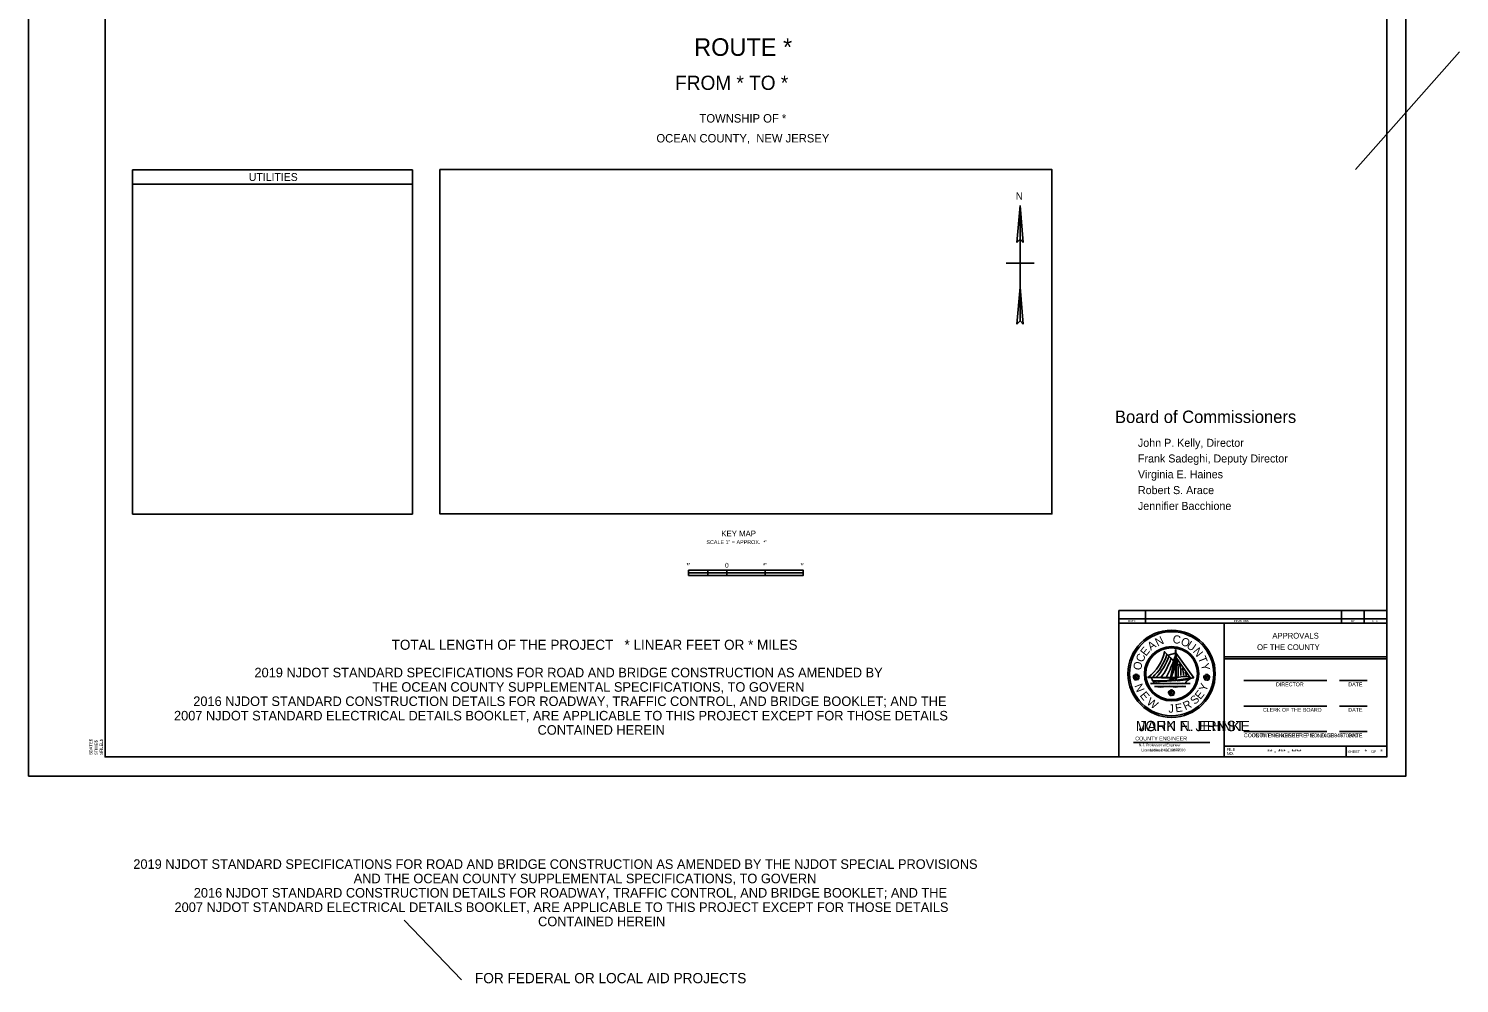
# Model space of a CAD drawing. Extents: x -51896 to -50062, y 9316 to 10514.
# Drawn here: x -51896 to -50774, y 9316 to 10064 of the extents above; entities that cross this region are included whole.
import ezdxf

# ---------------------------------------------------------------- set-up
doc = ezdxf.new("R2010")
doc.units = 0
for name, color, linetype in [('_Guidelines', 7, 'Continuous'), ('Default', 7, 'Continuous'), ('Level 1', 7, 'Continuous'), ('Level 47', 7, 'Continuous'), ('Plan - North Arrow', 7, 'Continuous'), ('TB - ON', 7, 'Continuous'), ('TB - Signed by John N Ernst', 7, 'Continuous'), ('TB - Signed by Mark F Jehnke', 7, 'Continuous')]:
    doc.layers.add(name, color=color, linetype=linetype)

msp = doc.modelspace()

# ---------------------------------------------------------------- linework, layer by layer
at = {"layer": '_Guidelines'}
for p, q in [((-50855, 9953.9), (-50773.6, 10046.3)), ((-51601.2, 9365.2), (-51556.2, 9318.4))]:
    msp.add_line(p, q, dxfattribs=at)
msp.add_lwpolyline([(-51895.6, 9478.3), (-50815.6, 9478.3), (-50815.6, 10198.3), (-51895.6, 10198.3)], close=True, dxfattribs=at)
at = {"layer": 'Default'}
msp.add_line((-51835.6, 9493.3), (-51835.6, 9503.3), dxfattribs=at)
at = {"layer": 'Level 1'}
for p, q in [((-51814.2, 9953.6), (-51594.5, 9953.6)), ((-51814.2, 9683.6), (-51814.2, 9953.6)), ((-51594.5, 9953.6), (-51594.5, 9683.6)), ((-51594.5, 9942.5), (-51814.2, 9942.5)), ((-51814.2, 9683.6), (-51594.5, 9683.6))]:
    msp.add_line(p, q, dxfattribs=at)
for points in [[(-51835.6, 10183.3), (-50830.6, 10183.3), (-50830.6, 9493.3), (-51835.6, 9493.3)], [(-51573.1, 9953.9), (-51093.1, 9953.9), (-51093.1, 9683.9), (-51573.1, 9683.9)], [(-51378.1, 9637.7), (-51363.1, 9637.7), (-51363.1, 9639.7), (-51378.1, 9639.7)], [(-51378.1, 9639.7), (-51363.1, 9639.7), (-51363.1, 9637.7), (-51378.1, 9637.7)], [(-51378.1, 9635.7), (-51363.1, 9635.7), (-51363.1, 9637.7), (-51378.1, 9637.7)], [(-51378.1, 9635.7), (-51363.1, 9635.7), (-51363.1, 9637.7), (-51378.1, 9637.7)], [(-51363.1, 9637.7), (-51348.1, 9637.7), (-51348.1, 9639.7), (-51363.1, 9639.7)], [(-51363.1, 9637.7), (-51348.1, 9637.7), (-51348.1, 9639.7), (-51363.1, 9639.7)], [(-51363.1, 9635.7), (-51348.1, 9635.7), (-51348.1, 9637.7), (-51363.1, 9637.7)], [(-51363.1, 9637.7), (-51348.1, 9637.7), (-51348.1, 9635.7), (-51363.1, 9635.7)], [(-51348.1, 9637.7), (-51318.1, 9637.7), (-51318.1, 9639.7), (-51348.1, 9639.7)], [(-51348.1, 9639.7), (-51318.1, 9639.7), (-51318.1, 9637.7), (-51348.1, 9637.7)], [(-51348.1, 9635.7), (-51318.1, 9635.7), (-51318.1, 9637.7), (-51348.1, 9637.7)], [(-51348.1, 9635.7), (-51318.1, 9635.7), (-51318.1, 9637.7), (-51348.1, 9637.7)], [(-51318.1, 9637.7), (-51288.1, 9637.7), (-51288.1, 9639.7), (-51318.1, 9639.7)], [(-51318.1, 9637.7), (-51288.1, 9637.7), (-51288.1, 9639.7), (-51318.1, 9639.7)], [(-51318.1, 9635.7), (-51288.1, 9635.7), (-51288.1, 9637.7), (-51318.1, 9637.7)], [(-51318.1, 9637.7), (-51288.1, 9637.7), (-51288.1, 9635.7), (-51318.1, 9635.7)]]:
    msp.add_lwpolyline(points, close=True, dxfattribs=at)
at = {"layer": 'Level 47'}
for p, q in [((-50831.1, 9595.4), (-50830.6, 9595.4)), ((-50830.6, 9595.4), (-50830.6, 9493.3)), ((-50830.6, 9595.4), (-50830.6, 9493.2)), ((-51005, 9575.6), (-50996.3, 9566.9)), ((-51004.8, 9575.8), (-50996.3, 9567.4)), ((-50996.2, 9574.7), (-51002.1, 9573.2)), ((-50996, 9574.3), (-51000.8, 9553.1)), ((-50996, 9574.3), (-51000.1, 9553.2)), ((-50997.9, 9569), (-50996.2, 9572.6)), ((-50996.3, 9571.4), (-50996.2, 9577.1)), ((-50996.3, 9553.5), (-50996.3, 9571.4)), ((-50995.8, 9571.4), (-50995.9, 9577.1)), ((-50995.9, 9574.9), (-50981.9, 9555.4)), ((-50995.8, 9553.5), (-50995.8, 9571.4)), ((-50995.7, 9571.3), (-50984.4, 9555)), ((-50958.1, 9571.7), (-50830.6, 9571.7)), ((-50958.1, 9570.2), (-50830.6, 9570.2)), ((-50996.3, 9555.5), (-51018.1, 9555.8)), ((-50996.3, 9555.1), (-51018.1, 9555.5)), ((-51015.8, 9550.8), (-50984.7, 9550.8)), ((-51009.9, 9551.3), (-51015.1, 9550.5)), ((-51015, 9555.3), (-51014.2, 9553.2)), ((-51012.6, 9548.6), (-50988.2, 9548.5)), ((-51007.9, 9548.1), (-51012.3, 9548.6)), ((-51005.5, 9550.6), (-51009.9, 9551.3)), ((-51001.1, 9548.8), (-51007.9, 9548.1)), ((-51000, 9551.2), (-51005.5, 9550.6)), ((-50994.3, 9555.5), (-51003.1, 9553)), ((-50996.5, 9548), (-51001.1, 9548.8)), ((-50994.6, 9550.6), (-51000, 9551.2)), ((-50990.8, 9548.9), (-50996.5, 9548)), ((-50990.8, 9551.2), (-50994.6, 9550.6)), ((-50984.7, 9550.8), (-50990.8, 9551.2)), ((-50988.2, 9548.5), (-50990.8, 9548.9)), ((-50984.6, 9555), (-50981.9, 9555.5)), ((-50984.6, 9554.7), (-50981.9, 9555.4)), ((-50942.7, 9553.2), (-50877.7, 9553.2)), ((-50867.7, 9553.2), (-50846, 9553.2)), ((-50942.7, 9533.2), (-50877.7, 9533.2)), ((-50867.7, 9533.2), (-50846, 9533.2)), ((-50942.7, 9513.2), (-50877.7, 9513.2)), ((-50867.7, 9513.2), (-50846, 9513.2))]:
    msp.add_line(p, q, dxfattribs=at)
for centre, radius in [((-50999.3, 9558.5), 34.2), ((-50999.3, 9558.5), 33), ((-50999.3, 9558.5), 21.3), ((-50999.3, 9558.5), 20.3), ((-51027, 9555.8), 0.573), ((-50971.8, 9555.7), 0.573), ((-50999.4, 9543.5), 0.573)]:
    msp.add_circle(centre, radius, dxfattribs=at)
for centre, radius, start, end in [((-51039.3, 9583.8), 35.5, 307.9044, 346.2123), ((-51039.3, 9583.8), 37.6, 311.6295, 344.3717), ((-51039.3, 9583.8), 39.5, 314.5286, 342.87), ((-51049.4, 9586.9), 52.2, 323.1533, 341.6611), ((-51004.9, 9575.7), 0.141, 39.7261, 230.2739), ((-50996, 9577.1), 0.156, 19.75, 182.7703), ((-51036, 9559.7), 41.9, 354.2243, 16.0469), ((-51240.6, 9668.6), 262.7, 334.5055, 337.59), ((-51082.2, 9585), 87.8, 340.3858, 348.1466), ((-51015.4, 9558.8), 23.4, 355.784, 18.8142), ((-51000.4, 9558), 10.5, 355.1604, 27.7837), ((-50994.4, 9556.8), 6.52, 2.6249, 29.2339), ((-51027.4, 9556), 1.92, 137.1576, 188.5747), ((-51029, 9555.7), 0.305, 188.5747, 249.3461), ((-51029, 9555.8), 0.422, 249.3461, 295.9329), ((-51028.6, 9554.7), 0.437, 121.0182, 155.6502), ((-51028.7, 9554.7), 0.305, 155.6502, 209.1576), ((-51027.3, 9555.5), 1.92, 209.1576, 260.5747), ((-51028.6, 9557.1), 0.305, 83.6502, 137.1576), ((-51028.9, 9555.7), 0.305, 295.9329, 1.1485), ((-51028.6, 9554.8), 0.305, 37.3592, 121.0182), ((-51028.6, 9556.9), 0.437, 49.0182, 83.6502), ((-51026.7, 9555.8), 1.92, 145.3592, 181.1485), ((-51026.9, 9556.1), 1.92, 217.3592, 253.1485), ((-51028.5, 9557), 0.305, 325.3592, 49.0182), ((-51027.8, 9557.7), 0.305, 116.5747, 177.3461), ((-51027.7, 9557.7), 0.422, 177.3461, 223.9329), ((-51027.7, 9557.6), 0.305, 223.9329, 289.1485), ((-51027, 9556.3), 1.92, 65.1576, 116.5747), ((-51027, 9555.5), 1.92, 73.3592, 109.1485), ((-51027.5, 9553.9), 0.305, 260.5747, 321.3461), ((-51027.5, 9554), 0.305, 7.9329, 73.1485), ((-51027.6, 9554), 0.422, 321.3461, 7.9329), ((-51026.5, 9554), 0.305, 109.3592, 193.0182), ((-51026.4, 9554), 0.437, 193.0182, 227.6502), ((-51026.5, 9553.9), 0.305, 227.6502, 281.1576), ((-51027.2, 9556.1), 1.92, 289.3592, 325.1485), ((-51026.4, 9557.6), 0.305, 253.3592, 337.0182), ((-51026.8, 9555.5), 1.92, 281.1576, 332.5747), ((-51026.4, 9557.7), 0.305, 11.6502, 65.1576), ((-51026.5, 9557.7), 0.437, 337.0182, 11.6502), ((-51025.6, 9557.1), 0.305, 151.9329, 217.1485), ((-51025.5, 9557), 0.422, 105.3461, 151.9329), ((-51027.3, 9555.7), 1.92, 1.3592, 37.1485), ((-51025.4, 9554.8), 0.305, 79.9329, 145.1485), ((-51025.5, 9557.1), 0.305, 44.5747, 105.3461), ((-51025.1, 9555.8), 0.305, 181.3592, 265.0182), ((-51025.4, 9554.7), 0.422, 33.3461, 79.9329), ((-51026.7, 9556), 1.92, 353.1576, 44.5747), ((-51025.1, 9555.9), 0.437, 265.0182, 299.6502), ((-51025.3, 9554.8), 0.305, 332.5747, 33.3461), ((-51025, 9555.8), 0.305, 299.6502, 353.1576), ((-51007.2, 9680.1), 127.1, 266.6979, 280.2311), ((-51020, 9547.6), 7.85, 25.6797, 45.8506), ((-51007.2, 9680.1), 127.4, 266.8543, 280.194), ((-51007.2, 9680.1), 127.8, 267.0182, 268.2401), ((-51007.2, 9680.1), 127.8, 275.5572, 279.6681), ((-50989.1, 9540.3), 16.1, 75.1755, 109.0388), ((-50981.5, 9547.4), 7.9, 113.61, 152.6948), ((-50972.1, 9555.8), 1.92, 137.1576, 188.5747), ((-50973.7, 9555.6), 0.305, 188.5747, 249.3461), ((-50973.7, 9555.7), 0.422, 249.3461, 295.9329), ((-50973.3, 9554.5), 0.437, 121.0182, 155.6502), ((-50973.4, 9554.6), 0.305, 155.6502, 209.1576), ((-50972, 9555.3), 1.92, 209.1576, 260.5747), ((-50973.3, 9556.9), 0.305, 83.6502, 137.1576), ((-50973.7, 9555.6), 0.305, 295.9329, 1.1485), ((-50973.3, 9554.6), 0.305, 37.3592, 121.0182), ((-50973.3, 9556.8), 0.437, 49.0182, 83.6502), ((-50971.4, 9555.6), 1.92, 145.3592, 181.1485), ((-50973.3, 9556.9), 0.305, 325.3592, 49.0182), ((-50971.6, 9556), 1.92, 217.3592, 253.1485), ((-50972.5, 9557.5), 0.305, 116.5747, 177.3461), ((-50972.4, 9557.5), 0.422, 177.3461, 223.9329), ((-50972.5, 9557.5), 0.305, 223.9329, 289.1485), ((-50971.8, 9556.1), 1.92, 65.1576, 116.5747), ((-50971.7, 9555.4), 1.92, 73.3592, 109.1485), ((-50972.3, 9553.8), 0.305, 260.5747, 321.3461), ((-50972.2, 9553.8), 0.305, 7.9329, 73.1485), ((-50972.3, 9553.8), 0.422, 321.3461, 7.9329), ((-50971.2, 9553.8), 0.305, 109.3592, 193.0182), ((-50971.1, 9553.9), 0.437, 193.0182, 227.6502), ((-50971.2, 9553.8), 0.305, 227.6502, 281.1576), ((-50972, 9555.9), 1.92, 289.3592, 325.1485), ((-50971.1, 9557.5), 0.305, 253.3592, 337.0182), ((-50971.5, 9555.4), 1.92, 281.1576, 332.5747), ((-50971.1, 9557.6), 0.305, 11.6502, 65.1576), ((-50971.2, 9557.5), 0.437, 337.0182, 11.6502), ((-50970.2, 9556.8), 0.422, 105.3461, 151.9329), ((-50970.3, 9556.9), 0.305, 151.9329, 217.1485), ((-50972.1, 9555.6), 1.92, 1.3592, 37.1485), ((-50970.1, 9554.7), 0.305, 79.9329, 145.1485), ((-50970.2, 9557), 0.305, 44.5747, 105.3461), ((-50969.8, 9555.6), 0.305, 181.3592, 265.0182), ((-50970.2, 9554.6), 0.422, 33.3461, 79.9329), ((-50971.4, 9555.8), 1.92, 353.1576, 44.5747), ((-50969.8, 9555.7), 0.437, 265.0182, 299.6502), ((-50970.1, 9554.6), 0.305, 332.5747, 33.3461), ((-50969.8, 9555.6), 0.305, 299.6502, 353.1576), ((-50999.8, 9543.6), 1.92, 137.1576, 188.5747), ((-51001.4, 9543.4), 0.305, 188.5747, 249.3461), ((-51001.3, 9543.5), 0.422, 249.3461, 295.9329), ((-51000.9, 9542.3), 0.437, 121.0182, 155.6502), ((-51001, 9542.4), 0.305, 155.6502, 209.1576), ((-50999.6, 9543.2), 1.92, 209.1576, 260.5747), ((-51001, 9544.7), 0.305, 83.6502, 137.1576), ((-51001.3, 9543.4), 0.305, 295.9329, 1.1485), ((-51001, 9542.4), 0.305, 37.3592, 121.0182), ((-50999.1, 9543.4), 1.92, 145.3592, 181.1485), ((-51001, 9544.6), 0.437, 49.0182, 83.6502), ((-51000.9, 9544.7), 0.305, 325.3592, 49.0182), ((-50999.2, 9543.8), 1.92, 217.3592, 253.1485), ((-51000.1, 9545.4), 0.305, 116.5747, 177.3461), ((-51000, 9545.4), 0.422, 177.3461, 223.9329), ((-51000.1, 9545.3), 0.305, 223.9329, 289.1485), ((-50999.4, 9543.9), 1.92, 65.1576, 116.5747), ((-50999.3, 9543.2), 1.92, 73.3592, 109.1485), ((-50999.9, 9541.6), 0.305, 260.5747, 321.3461), ((-50999.8, 9541.7), 0.305, 7.9329, 73.1485), ((-51000, 9541.6), 0.422, 321.3461, 7.9329), ((-50998.9, 9541.7), 0.305, 109.3592, 193.0182), ((-50998.7, 9541.7), 0.437, 193.0182, 227.6502), ((-50999.6, 9543.8), 1.92, 289.3592, 325.1485), ((-50998.8, 9541.6), 0.305, 227.6502, 281.1576), ((-50998.7, 9545.3), 0.305, 253.3592, 337.0182), ((-50999.1, 9543.2), 1.92, 281.1576, 332.5747), ((-50998.7, 9545.4), 0.305, 11.6502, 65.1576), ((-50998.8, 9545.4), 0.437, 337.0182, 11.6502), ((-50997.8, 9544.7), 0.422, 105.3461, 151.9329), ((-50997.9, 9544.7), 0.305, 151.9329, 217.1485), ((-50999.7, 9543.4), 1.92, 1.3592, 37.1485), ((-50997.8, 9542.5), 0.305, 79.9329, 145.1485), ((-50997.8, 9544.8), 0.305, 44.5747, 105.3461), ((-50997.5, 9543.4), 0.305, 181.3592, 265.0182), ((-50997.8, 9542.4), 0.422, 33.3461, 79.9329), ((-50999, 9543.6), 1.92, 353.1576, 44.5747), ((-50997.4, 9543.6), 0.437, 265.0182, 299.6502), ((-50997.7, 9542.4), 0.305, 332.5747, 33.3461), ((-50997.4, 9543.4), 0.305, 299.6502, 353.1576)]:
    msp.add_arc(centre, radius, start, end, dxfattribs=at)
at = {"layer": 'Plan - North Arrow'}
for p, q in [((-51118.1, 9925.7), (-51120.6, 9896.8)), ((-51118.1, 9925.7), (-51118.1, 9899.3)), ((-51115.6, 9896.8), (-51118.1, 9925.7)), ((-51118.1, 9899.3), (-51118.1, 9925.7)), ((-51118.1, 9899.3), (-51118.1, 9925.7)), ((-51120.6, 9896.8), (-51118.1, 9899.3)), ((-51118.1, 9899.3), (-51118.1, 9861.6)), ((-51118.1, 9899.3), (-51115.6, 9896.8)), ((-51118.1, 9880.5), (-51129, 9880.5)), ((-51118.1, 9880.5), (-51107.2, 9880.5)), ((-51120.6, 9832.7), (-51118.1, 9861.6)), ((-51118.1, 9861.6), (-51115.6, 9832.7)), ((-51118.1, 9835.2), (-51118.1, 9861.6)), ((-51118.1, 9835.2), (-51118.1, 9861.6)), ((-51118.1, 9861.6), (-51118.1, 9835.2)), ((-51118.1, 9835.2), (-51120.6, 9832.7)), ((-51115.6, 9832.7), (-51118.1, 9835.2))]:
    msp.add_line(p, q, dxfattribs=at)
at = {"layer": 'TB - ON'}
for p, q in [((-51040.6, 9608), (-50830.6, 9608)), ((-51040.6, 9598.3), (-51040.6, 9608)), ((-51019.7, 9598.3), (-51019.7, 9608)), ((-50866, 9598.3), (-50866, 9608)), ((-50848.3, 9598.3), (-50848.3, 9608)), ((-50830.6, 9598.3), (-50830.6, 9608)), ((-51040.6, 9601.5), (-50830.6, 9601.5)), ((-51040.6, 9598.3), (-50830.6, 9598.3)), ((-51040.6, 9493.3), (-51040.6, 9598.3)), ((-50958.1, 9493.2), (-50958.1, 9598.2)), ((-50830.6, 9501.8), (-50958.1, 9501.8)), ((-50862.4, 9501.8), (-50862.4, 9493.2))]:
    msp.add_line(p, q, dxfattribs=at)
at = {"layer": 'TB - Signed by John N Ernst'}
msp.add_line((-51029.3, 9504.7), (-50969.3, 9504.7), dxfattribs=at)
at = {"layer": 'TB - Signed by Mark F Jehnke'}
msp.add_line((-51029.3, 9504.7), (-50969.3, 9504.7), dxfattribs=at)

# ---------------------------------------------------------------- texts
at = {"layer": '_Guidelines'}
msp.add_text('FOR FEDERAL OR LOCAL AID PROJECTS', height=8, dxfattribs=at).set_placement((-51545.6, 9315.8))
at = {"layer": 'Level 1'}
for s, height, p in [('ROUTE *', 13.79, (-51373.7, 10043.1)), ('FROM * TO *', 11.156, (-51388.6, 10016.4)), ('TOWNSHIP OF *', 6.588, (-51369.5, 9990.8)), ('OCEAN COUNTY,  NEW JERSEY', 6.588, (-51403.3, 9975.2)), ('UTILITIES', 6.14, (-51722.9, 9945)), ('Board of Commissioners', 9.707, (-51043.7, 9755.2)), ('John P. Kelly, Director', 6.275, (-51025.7, 9736.5)), ('Frank Sadeghi, Deputy Director', 6.275, (-51025.7, 9724.2)), ('Virginia E. Haines', 6.275, (-51025.7, 9711.8)), ('Robert S. Arace', 6.275, (-51025.7, 9699.4)), ('Jennifier Bacchione', 6.275, (-51025.7, 9687)), ('SCALE 1" = APPROX.  *\'', 3.05, (-51364.1, 9660.2)), ("*'", 3.77, (-51379.8, 9641.7)), ('0', 3.77, (-51349.5, 9641.7)), ("*'", 3.77, (-51319.9, 9641.7)), ("*'", 3.77, (-51290.2, 9641.7)), ('TOTAL LENGTH OF THE PROJECT   * LINEAR FEET OR * MILES', 7.902, (-51610.9, 9577.3)), ('2019 NJDOT STANDARD SPECIFICATIONS FOR ROAD AND BRIDGE CONSTRUCTION AS AMENDED BY', 7.5, (-51718.5, 9555.7)), ('THE OCEAN COUNTY SUPPLEMENTAL SPECIFICATIONS, TO GOVERN', 7.5, (-51626.1, 9544.4)), ('2016 NJDOT STANDARD CONSTRUCTION DETAILS FOR ROADWAY, TRAFFIC CONTROL, AND BRIDGE BOOKLET; AND THE ', 7.5, (-51766.5, 9533.2)), ('2007 NJDOT STANDARD ELECTRICAL DETAILS BOOKLET, ARE APPLICABLE TO THIS PROJECT EXCEPT FOR THOSE DETAILS ', 7.5, (-51781.6, 9521.9)), ('CONTAINED HEREIN', 7.5, (-51496.5, 9510.7))]:
    msp.add_text(s, height=height, dxfattribs=at).set_placement(p)
for s, p in [('2019 NJDOT STANDARD SPECIFICATIONS FOR ROAD AND BRIDGE CONSTRUCTION AS AMENDED BY THE NJDOT SPECIAL PROVISIONS ', (-51813.5, 9405.5)), ('AND THE OCEAN COUNTY SUPPLEMENTAL SPECIFICATIONS, TO GOVERN', (-51640.7, 9394.2)), ('2016 NJDOT STANDARD CONSTRUCTION DETAILS FOR ROADWAY, TRAFFIC CONTROL, AND BRIDGE BOOKLET; AND THE ', (-51766.1, 9383)), ('2007 NJDOT STANDARD ELECTRICAL DETAILS BOOKLET, ARE APPLICABLE TO THIS PROJECT EXCEPT FOR THOSE DETAILS ', (-51781.2, 9371.7)), ('CONTAINED HEREIN', (-51496.1, 9360.5))]:
    msp.add_text(s, height=7.5, rotation=360, dxfattribs=at).set_placement(p)
at = {"layer": 'Level 47'}
for s, height, p in [('KEY MAP', 4.57, (-51352.4, 9666.2)), ('OF THE COUNTY', 4.5, (-50932.3, 9577.1)), ('APPROVALS', 4.5, (-50920.3, 9586.1)), ('DIRECTOR', 3, (-50917.4, 9548.7)), ('DATE', 3, (-50860.7, 9548.7)), ('CLERK OF THE BOARD', 3, (-50927.7, 9528.7)), ('DATE', 3, (-50860.7, 9528.7)), ('DATE', 3, (-50860.7, 9508.7)), ('FILE', 2.34, (-50956.2, 9497.9)), ('NO.', 2.34, (-50956.2, 9494.8)), ('** - *** - ****', 3.688, (-50924.3, 9495.7)), ('SHEET', 2.15, (-50861.4, 9496.4)), ('*', 3.69, (-50847.9, 9495.7)), ('OF', 2.15, (-50842.9, 9496.4)), ('*', 3.69, (-50835.7, 9495.7))]:
    msp.add_text(s, height=height, dxfattribs=at).set_placement(p)
for s, rotation, p in [('A', 34.3844, (-51015.6, 9576.5)), ('N', 25.8062, (-51010.3, 9579.8)), ('C', 351.4933, (-50998.8, 9582.7)), ('O', 334.3368, (-50992.8, 9581.8)), ('U', 325.7585, (-50988.1, 9579.3)), ('C', 68.6974, (-51021.7, 9567)), ('E', 51.5409, (-51019.4, 9571.9)), ('N', 308.6021, (-50983, 9575.9)), ('T', 291.4456, (-50978.8, 9570.9)), ('O', 77.2756, (-51023.4, 9560.8)), ('Y', 282.8674, (-50976.5, 9566)), ('N', 291.5886, (-51028.6, 9549.2)), ('Y', 68.8404, (-50972.2, 9544.1)), ('E', 308.7451, (-51024.6, 9541.4)), ('W', 325.9015, (-51019.4, 9535)), ('R', 25.9492, (-50988.5, 9529.8)), ('S', 43.1057, (-50981.1, 9533.9)), ('E', 51.6839, (-50976.7, 9537.9)), ('J', 0.2145, (-51001.8, 9528)), ('E', 8.7927, (-50996, 9528.2))]:
    msp.add_text(s, height=6.44, rotation=rotation, dxfattribs=at).set_placement(p)
at = {"layer": 'Plan - North Arrow'}
msp.add_text('N', height=5.78, dxfattribs=at).set_placement((-51121.5, 9930.2))
at = {"layer": 'TB - ON'}
for s, p in [('DATE', (-51033.4, 9599.1)), ('REVISIONS', (-50950.6, 9599.1)), ('BY', (-50858.6, 9599.1)), ('CHK.', (-50842.4, 9599.1))]:
    msp.add_text(s, height=1.56, dxfattribs=at).set_placement(p)
for s, p in [('$DATE$', (-51845.6, 9494.9)), ('$TIME$', (-51841.5, 9494.9)), ('$FILEL$', (-51837.4, 9494.9))]:
    msp.add_text(s, height=2.4, rotation=90, dxfattribs=at).set_placement(p)
at = {"layer": 'TB - Signed by John N Ernst'}
for s, height, p in [('JOHN N. ERNST', 8.08, (-51025.2, 9513.5)), ('N.J. Professional Engineer', 2, (-51025, 9501.7)), ('COUNTY ENGINEER  P.E. NO. 33347', 3, (-50936.6, 9508.7)), ('License No. 33347', 2, (-51015.9, 9497.7))]:
    msp.add_text(s, height=height, dxfattribs=at).set_placement(p)
msp.add_text('COUNTY ENGINEER', height=3.023, rotation=360, dxfattribs=at).set_placement((-51027.8, 9506.2))
at = {"layer": 'TB - Signed by Mark F Jehnke'}
for s, height, p in [('MARK F. JEHNKE', 8.08, (-51027.4, 9513.5)), ('N.J. Professional Engineer', 2, (-51025, 9501.7)), ('COUNTY ENGINEER  P.E. NO. 24GE04670300', 3, (-50942.6, 9508.7)), ('License No. 24GE04670300', 2, (-51023, 9497.7))]:
    msp.add_text(s, height=height, dxfattribs=at).set_placement(p)
msp.add_text('COUNTY ENGINEER', height=3.023, rotation=360, dxfattribs=at).set_placement((-51027.8, 9506.2))

doc.saveas('drawing.dxf')
